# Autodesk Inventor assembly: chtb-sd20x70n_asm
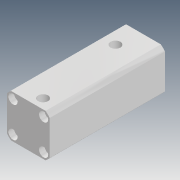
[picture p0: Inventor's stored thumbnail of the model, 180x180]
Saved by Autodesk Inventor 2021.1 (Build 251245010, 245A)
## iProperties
Company: Microsoft
Created: 2018-04
Part Number: chtb-sd20x70n_asm
Description: STEP AP214
Document SubType Name: Assembly
Designer: user
Title: chtb-sd20x70n_asm.STEP
Author: Windows
Revision Number: ÈÎºÎ
Sending System: SolidWorks 2015
Preprocessor: SwSTEP 2.0
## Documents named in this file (4)
- D:\Vault_2016\Projekty\Clamptek\Hydraulic\CHTB\CHTB-20\Inventor\CHTB-SD20x70N\chtb-sd20x70n_asm.iam
- D:\Vault_2016\Projekty\Clamptek\Hydraulic\CHTB\CHTB-20\Inventor\CHTB-SD20x70N\CHTB-SD20X70NBT.ipt
- D:\Vault_2016\Projekty\Clamptek\Hydraulic\CHTB\CHTB-20\Inventor\CHTB-SD20x70N\CHTB-SD20X70NHSG.ipt
- D:\Vault_2016\Projekty\Clamptek\Hydraulic\CHTB\CHTB-20\Inventor\CHTB-SD20x70N\QG.ipt
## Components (3 placed, 3 different names)
1. CHTB-SD20X70NBT_1
2. CHTB-SD20X70NHSG_2
3. QG_3
